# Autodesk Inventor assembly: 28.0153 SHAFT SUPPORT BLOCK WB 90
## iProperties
Created: 2007-06
Part Number: 28.0153 SHAFT SUPPORT BLOCK WB 90
Document SubType Name: Assembly
Designer: Andy Moles
Author: Andy Moles
